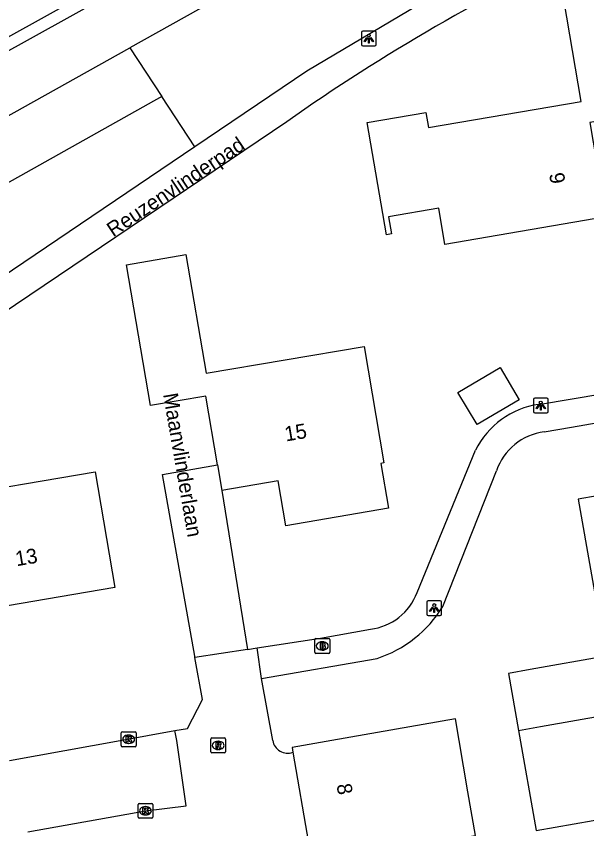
# Model space of a CAD drawing. Extents: x 162880 to 165536, y 384011 to 385179.
# Drawn here: x 163919 to 163957.3, y 384744.1 to 384798.8 of the extents above; entities that cross this region are included whole.
import ezdxf

# ---------------------------------------------------------------- set-up
doc = ezdxf.new("R2010")
doc.units = 0
for name, color, linetype in [('IMGEO_Brandkraan', 7, 'Continuous'), ('IMGEO_Gemengd_bos', 7, 'Continuous'), ('IMGEO_Kolk', 7, 'Continuous'), ('IMGEO_Lichtpunt', 7, 'Continuous'), ('IMGEO_Loofbos', 7, 'Continuous'), ('IMGEO_Muur', 7, 'Continuous'), ('IMGEO_Openbare_ruimte_label', 7, 'Continuous'), ('IMGEO_Pand', 7, 'Continuous'), ('IMGEO_Pand_nummerreeks', 7, 'Continuous'), ('IMGEO_Rijbaan_lokaal_open', 7, 'Continuous'), ('IMGEO_Rioolput', 7, 'Continuous'), ('IMGEO_Voetpad_open', 7, 'Continuous')]:
    doc.layers.add(name, color=color, linetype=linetype)

msp = doc.modelspace()

# ---------------------------------------------------------------- linework, layer by layer
at = {"layer": 'IMGEO_Brandkraan'}
for p, q in [((163939.038, 384755.937), (163939.038, 384756.789)), ((163939.113, 384756.863), (163939.965, 384756.863)), ((163940.039, 384756.789), (163940.039, 384755.937)), ((163939.526, 384756.643), (163939.551, 384756.643)), ((163939.965, 384755.863), (163939.113, 384755.863)), ((163939.549, 384756.083), (163939.524, 384756.083))]:
    msp.add_line(p, q, dxfattribs=at)
for points in [[(163939.038, 384755.937), (163939.038, 384756.789)], [(163939.113, 384756.863), (163939.965, 384756.863)], [(163940.039, 384756.789), (163940.039, 384755.937)], [(163939.386, 384756.563), (163939.386, 384756.163), (163939.599, 384756.163)], [(163939.617, 384756.563), (163939.386, 384756.563)], [(163939.565, 384756.482), (163939.511, 384756.482), (163939.511, 384756.406)], [(163939.511, 384756.406), (163939.564, 384756.406)], [(163939.573, 384756.33), (163939.511, 384756.33), (163939.511, 384756.249)], [(163939.511, 384756.249), (163939.573, 384756.249)], [(163939.965, 384755.863), (163939.113, 384755.863)]]:
    msp.add_lwpolyline(points, dxfattribs=at)
for centre, radius, start, end in [((163939.115, 384756.787), 0.0765, 91.552, 178.448), ((163939.115, 384756.787), 0.0765, 91.552, 178.448), ((163939.963, 384756.787), 0.0765, 1.552, 88.448), ((163939.963, 384756.787), 0.0765, 1.552, 88.448), ((163939.566, 384756.444), 0.0379, 267.8285, 90.9355), ((163939.574, 384756.289), 0.0404, 269.8759, 90.5077), ((163939.605, 384756.414), 0.251, 268.6676, 293.5347), ((163939.621, 384756.418), 0.145, 59.4692, 91.5367), ((163939.646, 384756.465), 0.0922, 285.5137, 58.1501), ((163939.651, 384756.273), 0.105, 301.3115, 78.989), ((163939.115, 384755.939), 0.0765, 181.552, 268.448), ((163939.115, 384755.939), 0.0765, 181.552, 268.448), ((163939.963, 384755.939), 0.0765, 271.552, 358.448), ((163939.963, 384755.939), 0.0765, 271.552, 358.448)]:
    msp.add_arc(centre, radius, start, end, dxfattribs=at)
for centre, major_axis, ratio, start_param, end_param in [((163939.525, 384756.363), (-0.387, 0.002), 0.722429, 4.712389, 7.853982), ((163939.55, 384756.363), (-0.39, 0.002), 0.717154, 1.570796, 4.712389)]:
    msp.add_ellipse(centre, major_axis=major_axis, ratio=ratio, start_param=start_param, end_param=end_param, dxfattribs=at)
at = {"layer": 'IMGEO_Gemengd_bos'}
msp.add_lwpolyline([(163928.738, 384793.357), (163895.604, 384774.738), (163891.742, 384771.979), (163891.515, 384769.969), (163891.098, 384768.108), (163890.489, 384766.3), (163889.694, 384764.565), (163888.722, 384762.923), (163887.584, 384761.392), (163882.713, 384756.212)], dxfattribs=at)
at = {"layer": 'IMGEO_Kolk'}
for p, q in [((163926.015, 384749.658), (163926.015, 384750.51)), ((163926.09, 384750.584), (163926.942, 384750.584)), ((163926.503, 384750.364), (163926.528, 384750.364)), ((163927.016, 384750.51), (163927.016, 384749.658)), ((163926.942, 384749.584), (163926.09, 384749.584)), ((163926.526, 384749.804), (163926.501, 384749.804)), ((163927.218, 384745.768), (163928.07, 384745.768)), ((163927.143, 384744.842), (163927.143, 384745.694)), ((163927.631, 384745.548), (163927.656, 384745.548)), ((163928.144, 384745.694), (163928.144, 384744.842)), ((163928.07, 384744.768), (163927.218, 384744.768)), ((163927.654, 384744.988), (163927.629, 384744.988))]:
    msp.add_line(p, q, dxfattribs=at)
for points in [[(163926.015, 384749.658), (163926.015, 384750.51)], [(163926.09, 384750.584), (163926.942, 384750.584)], [(163926.336, 384750.284), (163926.459, 384750.284), (163926.459, 384750.133), (163926.589, 384750.284), (163926.753, 384750.284), (163926.607, 384750.133), (163926.76, 384749.884), (163926.608, 384749.884), (163926.523, 384750.048), (163926.459, 384749.981), (163926.459, 384749.884), (163926.336, 384749.884), (163926.336, 384750.284)], [(163927.016, 384750.51), (163927.016, 384749.658)], [(163926.942, 384749.584), (163926.09, 384749.584)], [(163927.218, 384745.768), (163928.07, 384745.768)], [(163927.143, 384744.842), (163927.143, 384745.694)], [(163927.464, 384745.468), (163927.587, 384745.468), (163927.587, 384745.317), (163927.717, 384745.468), (163927.881, 384745.468), (163927.735, 384745.317), (163927.888, 384745.068), (163927.736, 384745.068), (163927.651, 384745.232), (163927.587, 384745.165), (163927.587, 384745.068), (163927.464, 384745.068), (163927.464, 384745.468)], [(163928.144, 384745.694), (163928.144, 384744.842)], [(163928.07, 384744.768), (163927.218, 384744.768)]]:
    msp.add_lwpolyline(points, dxfattribs=at)
for centre, start, end in [((163926.092, 384750.508), 91.552, 178.448), ((163926.092, 384750.508), 91.552, 178.448), ((163926.94, 384750.508), 1.552, 88.448), ((163926.94, 384750.508), 1.552, 88.448), ((163926.092, 384749.66), 181.552, 268.448), ((163926.092, 384749.66), 181.552, 268.448), ((163926.94, 384749.66), 271.552, 358.448), ((163926.94, 384749.66), 271.552, 358.448), ((163927.22, 384745.692), 91.552, 178.448), ((163927.22, 384745.692), 91.552, 178.448), ((163928.068, 384745.692), 1.552, 88.448), ((163928.068, 384745.692), 1.552, 88.448), ((163927.22, 384744.844), 181.552, 268.448), ((163927.22, 384744.844), 181.552, 268.448), ((163928.068, 384744.844), 271.552, 358.448), ((163928.068, 384744.844), 271.552, 358.448)]:
    msp.add_arc(centre, 0.0765, start, end, dxfattribs=at)
for centre, major_axis, ratio, start_param, end_param in [((163926.502, 384750.084), (-0.387, 0.002), 0.722429, 4.712389, 7.853982), ((163926.527, 384750.084), (-0.39, 0.002), 0.717154, 1.570796, 4.712389), ((163927.63, 384745.268), (-0.387, 0.002), 0.722429, 4.712389, 7.853982), ((163927.655, 384745.268), (-0.39, 0.002), 0.717154, 1.570796, 4.712389)]:
    msp.add_ellipse(centre, major_axis=major_axis, ratio=ratio, start_param=start_param, end_param=end_param, dxfattribs=at)
at = {"layer": 'IMGEO_Lichtpunt'}
for p, q in [((163943.073, 384797.746), (163942.265, 384797.746)), ((163943.073, 384797.746), (163942.265, 384797.746)), ((163942.171, 384797.651), (163942.171, 384796.844)), ((163942.171, 384797.651), (163942.171, 384796.844)), ((163943.167, 384796.844), (163943.167, 384797.651)), ((163943.167, 384796.844), (163943.167, 384797.651)), ((163942.265, 384796.75), (163943.073, 384796.75)), ((163942.265, 384796.75), (163943.073, 384796.75)), ((163953.737, 384772.953), (163953.737, 384772.146)), ((163953.737, 384772.953), (163953.737, 384772.146)), ((163954.639, 384773.048), (163953.831, 384773.048)), ((163954.639, 384773.048), (163953.831, 384773.048)), ((163954.733, 384772.146), (163954.733, 384772.953)), ((163954.733, 384772.146), (163954.733, 384772.953)), ((163953.831, 384772.052), (163954.639, 384772.052)), ((163953.831, 384772.052), (163954.639, 384772.052)), ((163947.474, 384759.411), (163946.666, 384759.411)), ((163947.474, 384759.411), (163946.666, 384759.411)), ((163946.572, 384759.316), (163946.572, 384758.509)), ((163946.572, 384759.316), (163946.572, 384758.509)), ((163947.568, 384758.509), (163947.568, 384759.316)), ((163947.568, 384758.509), (163947.568, 384759.316)), ((163946.666, 384758.415), (163947.474, 384758.415)), ((163946.666, 384758.415), (163947.474, 384758.415))]:
    msp.add_line(p, q, dxfattribs=at)
for points in [[(163942.545, 384797.315), (163942.584, 384797.287), (163942.396, 384797.025), (163942.358, 384797.052), (163942.545, 384797.315)], [(163942.647, 384797.267), (163942.694, 384797.267), (163942.694, 384796.945), (163942.647, 384796.945), (163942.647, 384797.267)], [(163942.757, 384797.287), (163942.795, 384797.314), (163942.982, 384797.052), (163942.943, 384797.024), (163942.757, 384797.287)], [(163954.111, 384772.617), (163954.15, 384772.589), (163953.962, 384772.327), (163953.924, 384772.354), (163954.111, 384772.617)], [(163954.213, 384772.569), (163954.26, 384772.569), (163954.26, 384772.247), (163954.213, 384772.247), (163954.213, 384772.569)], [(163954.323, 384772.589), (163954.361, 384772.616), (163954.548, 384772.354), (163954.509, 384772.326), (163954.323, 384772.589)], [(163946.946, 384758.98), (163946.985, 384758.952), (163946.797, 384758.69), (163946.759, 384758.717), (163946.946, 384758.98)], [(163947.048, 384758.932), (163947.095, 384758.932), (163947.095, 384758.61), (163947.048, 384758.61), (163947.048, 384758.932)], [(163947.158, 384758.952), (163947.196, 384758.979), (163947.383, 384758.717), (163947.344, 384758.689), (163947.158, 384758.952)]]:
    msp.add_lwpolyline(points, dxfattribs=at)
for centre in [(163942.67, 384797.449), (163954.236, 384772.751), (163947.071, 384759.114)]:
    msp.add_circle(centre, 0.0994, dxfattribs=at)
for centre, start, end in [((163942.265, 384797.651), 90, 180), ((163942.265, 384797.651), 90, 180), ((163943.073, 384797.651), 0, 90), ((163943.073, 384797.651), 0, 90), ((163942.265, 384796.844), 180, 270), ((163942.265, 384796.844), 180, 270), ((163943.073, 384796.844), 270, 0), ((163943.073, 384796.844), 270, 360), ((163953.831, 384772.953), 90, 180), ((163953.831, 384772.953), 90, 180), ((163954.639, 384772.953), 0, 90), ((163954.639, 384772.953), 0, 90), ((163953.831, 384772.146), 180, 270), ((163953.831, 384772.146), 180, 270), ((163954.639, 384772.146), 270, 0), ((163954.639, 384772.146), 270, 360), ((163946.666, 384759.316), 90, 180), ((163946.666, 384759.316), 90, 180), ((163947.474, 384759.316), 0, 90), ((163947.474, 384759.316), 0, 90), ((163946.666, 384758.509), 180, 270), ((163946.666, 384758.509), 180, 270), ((163947.474, 384758.509), 270, 0), ((163947.474, 384758.509), 270, 360)]:
    msp.add_arc(centre, 0.0946, start, end, dxfattribs=at)
at = {"layer": 'IMGEO_Loofbos'}
for points in [[(163943.747, 384806.221), (163926.594, 384796.628)], [(163832.961, 384744.266), (163843.216, 384750), (163926.594, 384796.628)], [(163926.594, 384796.628), (163928.738, 384793.357)], [(163930.97, 384789.954), (163928.738, 384793.357)]]:
    msp.add_lwpolyline(points, dxfattribs=at)
at = {"layer": 'IMGEO_Muur'}
for points in [[(164200.612, 384942.085), (164200.456, 384942.424), (164096.894, 384894.556), (164097.59, 384893.077), (164094.686, 384891.713), (164094.002, 384893.195), (164090.38, 384891.428), (164028.566, 384858.623), (164029.317, 384857.211), (164003.031, 384843.382), (164002.673, 384844.106), (163992.862, 384838.663), (163904.353, 384789.557), (163905.165, 384788.158), (163898.84, 384784.624), (163898.055, 384786.032), (163851.73, 384760.24), (163852.526, 384758.821), (163848.3, 384756.508), (163847.517, 384757.905), (163830.64, 384748.494)], [(163993.285, 384837.971), (163905.468, 384789.249), (163906.278, 384787.853), (163898.528, 384783.521), (163897.742, 384784.931), (163852.834, 384759.928), (163853.633, 384758.504), (163847.985, 384755.413), (163847.206, 384756.804), (163831.618, 384748.116), (163832.961, 384744.266)]]:
    msp.add_lwpolyline(points, dxfattribs=at)
at = {"layer": 'IMGEO_Pand'}
for points in [[(163958.613, 384785.239), (163947.786, 384783.397), (163947.374, 384785.824), (163944.001, 384785.25), (163944.195, 384784.105), (163943.852, 384784.047), (163942.567, 384791.594), (163946.507, 384792.265), (163946.679, 384791.254), (163956.958, 384793.003), (163955.603, 384800.964), (163959.502, 384801.627), (163961.106, 384792.202), (163957.531, 384791.593), (163958.613, 384785.239)], [(163932.496, 384768.566), (163931.71, 384773.186), (163927.983, 384772.552), (163926.371, 384782.025), (163930.358, 384782.704), (163931.717, 384774.719), (163942.354, 384776.529), (163943.688, 384768.693), (163943.467, 384768.655), (163943.982, 384765.63), (163937.081, 384764.456), (163936.566, 384767.481), (163932.79, 384766.839)], [(163952.789, 384772.936), (163949.947, 384771.261), (163948.666, 384773.435), (163951.508, 384775.11), (163952.789, 384772.936)], [(163909.385, 384768.821), (163909.013, 384771.037), (163912.76, 384771.671), (163913.136, 384769.459), (163913.675, 384766.288), (163924.251, 384768.088), (163925.577, 384760.295), (163914.669, 384758.439), (163914.03, 384762.197), (163910.61, 384761.615)], [(163958.376, 384771.452), (163959.198, 384766.669), (163957.128, 384766.313), (163956.746, 384766.245), (163958.616, 384755.673), (163953.533, 384754.774), (163952.058, 384754.514), (163952.738, 384750.674)], [(163932.496, 384768.566), (163932.79, 384766.839)], [(163952.738, 384750.674), (163953.931, 384743.934), (163959.034, 384744.838), (163959.873, 384740.096), (163965.714, 384741.069), (163970.387, 384741.829), (163969.029, 384749.504), (163961.369, 384748.149), (163961.061, 384750), (163960.734, 384751.96), (163960.714, 384752.08)], [(163952.738, 384750.674), (163954.213, 384750.934), (163960.714, 384752.08)], [(163936.733, 384733.425), (163940.532, 384734.062), (163939.177, 384741.782), (163949.839, 384743.614), (163949.338, 384746.539), (163948.743, 384750), (163948.492, 384751.457), (163940.189, 384750), (163937.505, 384749.529), (163937.56, 384749.211)], [(163937.56, 384749.211), (163938.606, 384743.121), (163935.25, 384742.544)]]:
    msp.add_lwpolyline(points, dxfattribs=at)
at = {"layer": 'IMGEO_Rijbaan_lokaal_open'}
for points in [[(163930.976, 384755.577), (163930.958, 384755.677), (163928.801, 384767.914), (163932.496, 384768.566)], [(163932.79, 384766.839), (163934.512, 384756.128)], [(163934.512, 384756.128), (163930.976, 384755.577)], [(163918.495, 384748.657), (163925.94, 384750), (163929.624, 384750.664)], [(163919.73, 384743.856), (163927.644, 384745.267), (163930.393, 384745.609), (163929.752, 384750), (163929.624, 384750.664)]]:
    msp.add_lwpolyline(points, dxfattribs=at)
at = {"layer": 'IMGEO_Rioolput'}
for p, q in [((163932.036, 384749.247), (163932.036, 384750.099)), ((163932.111, 384750.173), (163932.963, 384750.173)), ((163933.037, 384750.099), (163933.037, 384749.247)), ((163932.524, 384749.953), (163932.549, 384749.953)), ((163932.963, 384749.173), (163932.111, 384749.173)), ((163932.547, 384749.393), (163932.522, 384749.393))]:
    msp.add_line(p, q, dxfattribs=at)
for points in [[(163932.036, 384749.247), (163932.036, 384750.099)], [(163932.111, 384750.173), (163932.963, 384750.173)], [(163933.037, 384750.099), (163933.037, 384749.247)], [(163932.625, 384749.871), (163932.373, 384749.873), (163932.373, 384749.473)], [(163932.373, 384749.473), (163932.497, 384749.473), (163932.497, 384749.635), (163932.508, 384749.635)], [(163932.551, 384749.792), (163932.497, 384749.792), (163932.497, 384749.711)], [(163932.497, 384749.711), (163932.549, 384749.711)], [(163932.555, 384749.606), (163932.626, 384749.473), (163932.766, 384749.473), (163932.701, 384749.599)], [(163932.963, 384749.173), (163932.111, 384749.173)]]:
    msp.add_lwpolyline(points, dxfattribs=at)
for centre, radius, start, end in [((163932.113, 384750.097), 0.0765, 91.552, 178.448), ((163932.113, 384750.097), 0.0765, 91.552, 178.448), ((163932.961, 384750.097), 0.0765, 1.552, 88.448), ((163932.961, 384750.097), 0.0765, 1.552, 88.448), ((163932.507, 384749.582), 0.0533, 26.0293, 88.6989), ((163932.533, 384749.9), 0.19, 274.7715, 282.9687), ((163932.557, 384749.696), 0.0964, 77.0061, 93.1865), ((163932.571, 384749.753), 0.0378, 276.6634, 79.6772), ((163932.624, 384749.761), 0.109, 350.3612, 89.416), ((163932.622, 384749.761), 0.112, 277.5842, 350.9817), ((163932.606, 384749.546), 0.108, 29.5134, 73.7905), ((163932.113, 384749.249), 0.0765, 181.552, 268.448), ((163932.113, 384749.249), 0.0765, 181.552, 268.448), ((163932.961, 384749.249), 0.0765, 271.552, 358.448), ((163932.961, 384749.249), 0.0765, 271.552, 358.448)]:
    msp.add_arc(centre, radius, start, end, dxfattribs=at)
for centre, major_axis, ratio, start_param, end_param in [((163932.523, 384749.673), (-0.387, 0.002), 0.722429, 4.712389, 7.853982), ((163932.548, 384749.673), (-0.39, 0.002), 0.717154, 1.570796, 4.712389)]:
    msp.add_ellipse(centre, major_axis=major_axis, ratio=ratio, start_param=start_param, end_param=end_param, dxfattribs=at)
at = {"layer": 'IMGEO_Voetpad_open'}
for points in [[(163947.204, 384800.246), (163938.504, 384795.047), (163930.97, 384789.954)], [(163937.143, 384791.65), (163896.829, 384764.446)], [(163930.97, 384789.954), (163895.67, 384766.092)], [(163954.09, 384772.628), (163967.145, 384774.817)], [(163954.46, 384770.78), (163956.306, 384771.096), (163958.096, 384771.404), (163958.376, 384771.452)], [(163945.921, 384759.968), (163949.848, 384769.535)], [(163947.645, 384759.027), (163951.255, 384768.154)], [(163935.149, 384756.228), (163939.422, 384756.894), (163942.775, 384757.492)], [(163934.512, 384756.128), (163935.149, 384756.228)], [(163935.448, 384754.164), (163935.149, 384756.228)], [(163929.624, 384750.664), (163930.464, 384750.816), (163931.473, 384752.761), (163930.976, 384755.577)], [(163935.448, 384754.164), (163943.225, 384755.525)], [(163936.204, 384750), (163935.448, 384754.164)]]:
    msp.add_lwpolyline(points, dxfattribs=at)
for centre, radius, start, end in [((164013.196, 384683.727), 132.028, 114.84485, 125.17241), ((163954.932, 384767.018), 5.673, 98.5335, 153.6608), ((163954.996, 384766.857), 3.96, 97.7814, 160.8772), ((163942.331, 384761.293), 3.826, 276.6607, 339.747), ((163940.707, 384763.243), 8.118, 288.0665, 328.7136), ((163937.209, 384750.168), 1.019, 189.5011, 290.1122)]:
    msp.add_arc(centre, radius, start, end, dxfattribs=at)

# ---------------------------------------------------------------- texts
at = {"layer": 'IMGEO_Openbare_ruimte_label'}
for s, rotation, p in [('Reuzenvlinderpad', 33.833, (163925.47, 384783.858)), ('Maanvlinderlaan', 279.7824, (163928.825, 384773.304))]:
    msp.add_text(s, height=1, rotation=rotation, dxfattribs=at).set_placement(p)
at = {"layer": 'IMGEO_Pand_nummerreeks'}
for s, rotation, p in [('9', 279.664, (163954.792, 384788.137)), ('15', 9.6492, (163937.092, 384770.126)), ('13', 9.6564, (163918.976, 384761.728)), ('8', 279.7492, (163940.493, 384747.019))]:
    msp.add_text(s, height=1, rotation=rotation, dxfattribs=at).set_placement(p)

doc.saveas('drawing.dxf')
